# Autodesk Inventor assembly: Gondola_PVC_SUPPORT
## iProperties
Shininess: 64.0
Length Units: 11272
Angle Units: 11279
Time Units: 11290
Mass Units: 11286
Length Display Precision: 3
Angle Display Precision: 2
Compacted: True
Part Number: Gondola_PVC_SUPPORT
Document SubType Name: Assembly
Created: 2004-08
Designer: John Blackburn
Manufacturer: Standard
Standards Organization: Custom
Density: 0.0
Volumn: 0.0
Area: 0.0
PropertySet Name: Model Information
Control State: 0
Master: False
Checked Out: False
Author: John Blackburn
